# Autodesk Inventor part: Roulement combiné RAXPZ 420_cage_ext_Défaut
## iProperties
Shininess: 64.0
Length Units: 11269
Angle Units: 11279
Time Units: 11290
Mass Units: 11283
Length Display Precision: 3
Angle Display Precision: 2
Compacted: True
Part Number: Roulement combiné RAXPZ 420_cage_ext_Défaut
Document SubType Name: Modeling
Created: 2006-01
Material: Par défaut
Designer: riri
Density: 0.0
Volumn: 0.0
Area: 0.0
PropertySet Name: Model Information
Control State: 0
Master: False
Checked Out: False
Author: riri
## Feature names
1. Base1
